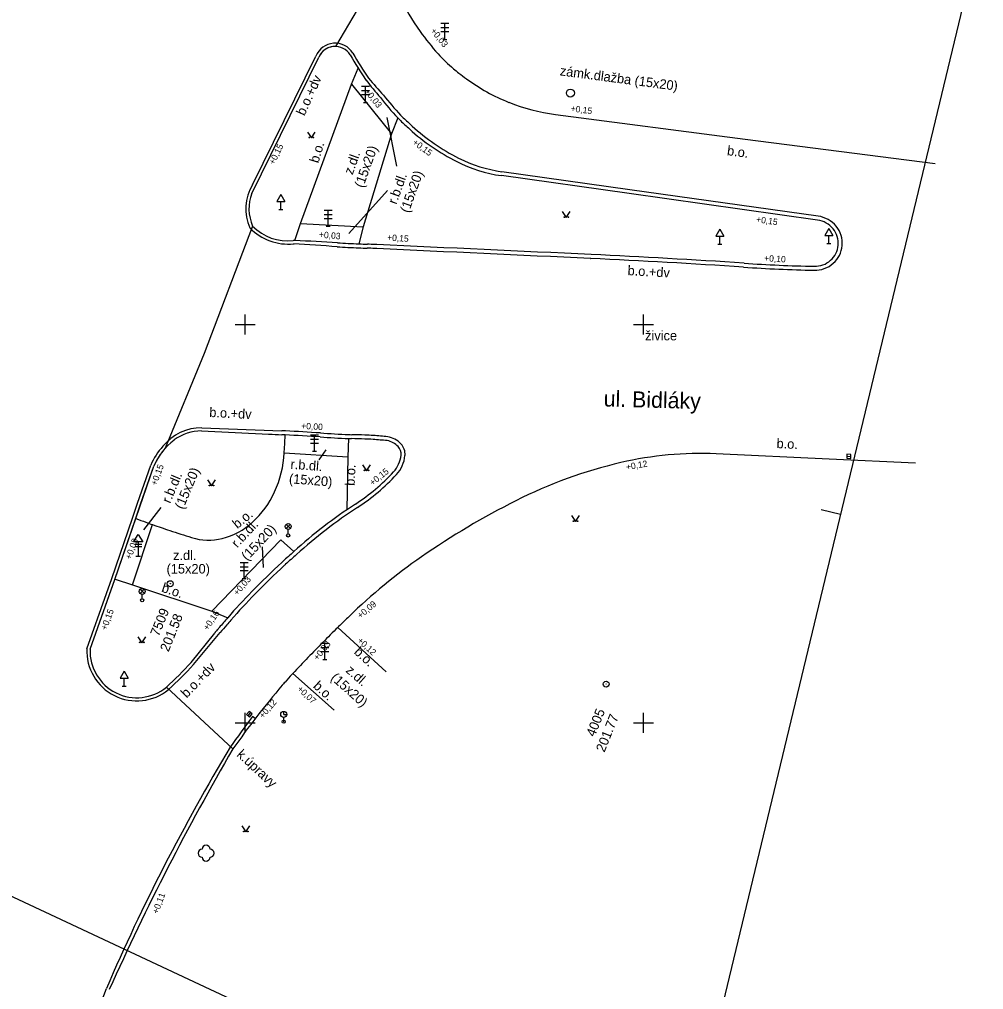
# Model space of a CAD drawing. Extents: x -599151 to -598424, y -1163476 to -1161924.
# Drawn here: x -598689.2 to -598628.7, y -1162691.7 to -1162630.9 of the extents above; entities that cross this region are included whole.
import ezdxf

# ---------------------------------------------------------------- set-up
doc = ezdxf.new("R2010")
doc.units = 0
for name, color, linetype in [('Vrstva 1', 7, 'Continuous'), ('Vrstva 14', 7, 'Continuous'), ('Vrstva 19', 7, 'Continuous'), ('Vrstva 2', 7, 'Continuous'), ('Vrstva 25', 7, 'Continuous'), ('Vrstva 29', 7, 'Continuous'), ('Vrstva 34', 7, 'Continuous'), ('Vrstva 42', 7, 'Continuous'), ('Vrstva 44', 7, 'Continuous'), ('Vrstva 49', 7, 'Continuous'), ('Vrstva 50', 7, 'Continuous'), ('Vrstva 62', 7, 'Continuous'), ('Vrstva 63', 7, 'Continuous'), ('Vrstva 7', 7, 'Continuous')]:
    doc.layers.add(name, color=color, linetype=linetype)

msp = doc.modelspace()

# ---------------------------------------------------------------- linework, layer by layer
at = {"layer": 'Vrstva 1'}
for p, q in [((-598563.987, -1162355.651), (-598649.916, -1162712.964)), ((-598637.64, -1162661.919), (-598638.855, -1162661.627)), ((-598640.084, -1162709.057), (-598707.36, -1162677.641))]:
    msp.add_line(p, q, dxfattribs=at)
at = {"layer": 'Vrstva 14'}
for points in [[(-598671.097, -1162637.921), (-598670.847, -1162638.296), (-598670.597, -1162637.921)], [(-598655.099, -1162642.92), (-598654.849, -1162643.295), (-598654.599, -1162642.92)], [(-598667.638, -1162658.805), (-598667.388, -1162659.18), (-598667.138, -1162658.805)], [(-598677.364, -1162659.751), (-598677.114, -1162660.126), (-598676.864, -1162659.751)], [(-598654.519, -1162661.988), (-598654.269, -1162662.363), (-598654.019, -1162661.988)], [(-598681.734, -1162669.597), (-598681.484, -1162669.972), (-598681.234, -1162669.597)], [(-598675.206, -1162681.467), (-598674.956, -1162681.842), (-598674.706, -1162681.467)]]:
    msp.add_lwpolyline(points, dxfattribs=at)
for centre, radius in [((-598670.972, -1162638.271), 0.025), ((-598670.722, -1162638.271), 0.025), ((-598654.974, -1162643.27), 0.025), ((-598654.724, -1162643.27), 0.025), ((-598667.513, -1162659.155), 0.025), ((-598667.263, -1162659.155), 0.025), ((-598677.239, -1162660.101), 0.025), ((-598676.989, -1162660.101), 0.025), ((-598654.394, -1162662.338), 0.025), ((-598654.144, -1162662.338), 0.025), ((-598681.609, -1162669.947), 0.025), ((-598681.359, -1162669.947), 0.025), ((-598675.081, -1162681.817), 0.025), ((-598674.831, -1162681.817), 0.025), ((-598677.45, -1162683.181), 0.00025)]:
    msp.add_circle(centre, radius, dxfattribs=at)
for centre, start, end in [((-598677.45, -1162682.931), 0, 179.99999), ((-598677.7, -1162683.181), 89.99999, 269.99999), ((-598677.2, -1162683.181), 270, 89.99999), ((-598677.45, -1162683.431), 179.99999, 359.99999)]:
    msp.add_arc(centre, 0.25, start, end, dxfattribs=at)
at = {"layer": 'Vrstva 19'}
for p, q in [((-598662.22, -1162631.121), (-598662.72, -1162631.121)), ((-598662.72, -1162631.371), (-598662.22, -1162631.371)), ((-598662.47, -1162632.121), (-598662.47, -1162631.121)), ((-598662.72, -1162631.621), (-598662.22, -1162631.621)), ((-598662.595, -1162632.121), (-598662.345, -1162632.121)), ((-598667.19, -1162635.07), (-598667.69, -1162635.07)), ((-598667.44, -1162636.07), (-598667.44, -1162635.07)), ((-598667.69, -1162635.32), (-598667.19, -1162635.32)), ((-598667.69, -1162635.57), (-598667.19, -1162635.57)), ((-598667.565, -1162636.07), (-598667.315, -1162636.07)), ((-598672.76, -1162641.847), (-598673.01, -1162642.28)), ((-598672.76, -1162641.847), (-598672.51, -1162642.28)), ((-598673.01, -1162642.28), (-598672.51, -1162642.28)), ((-598672.76, -1162642.78), (-598672.76, -1162642.28)), ((-598672.885, -1162642.78), (-598672.635, -1162642.78)), ((-598669.54, -1162642.84), (-598670.04, -1162642.84)), ((-598670.04, -1162643.09), (-598669.54, -1162643.09)), ((-598669.79, -1162643.84), (-598669.79, -1162642.84)), ((-598670.04, -1162643.34), (-598669.54, -1162643.34)), ((-598669.915, -1162643.84), (-598669.665, -1162643.84)), ((-598645.22, -1162644.017), (-598645.47, -1162644.45)), ((-598645.22, -1162644.017), (-598644.97, -1162644.45)), ((-598638.38, -1162643.978), (-598638.63, -1162644.411)), ((-598638.38, -1162643.978), (-598638.13, -1162644.411)), ((-598645.47, -1162644.45), (-598644.97, -1162644.45)), ((-598645.345, -1162644.95), (-598645.095, -1162644.95)), ((-598645.22, -1162644.95), (-598645.22, -1162644.45)), ((-598638.63, -1162644.411), (-598638.13, -1162644.411)), ((-598638.505, -1162644.911), (-598638.255, -1162644.911)), ((-598638.38, -1162644.911), (-598638.38, -1162644.411)), ((-598670.39, -1162656.95), (-598670.89, -1162656.95)), ((-598670.64, -1162657.95), (-598670.64, -1162656.95)), ((-598670.89, -1162657.2), (-598670.39, -1162657.2)), ((-598670.89, -1162657.45), (-598670.39, -1162657.45)), ((-598670.765, -1162657.95), (-598670.515, -1162657.95)), ((-598674.81, -1162664.95), (-598675.31, -1162664.95)), ((-598675.06, -1162665.95), (-598675.06, -1162664.95)), ((-598675.31, -1162665.2), (-598674.81, -1162665.2)), ((-598675.31, -1162665.45), (-598674.81, -1162665.45)), ((-598675.185, -1162665.95), (-598674.935, -1162665.95)), ((-598669.75, -1162670.02), (-598670.25, -1162670.02)), ((-598670.25, -1162670.27), (-598669.75, -1162670.27)), ((-598670.25, -1162670.52), (-598669.75, -1162670.52)), ((-598670, -1162671.02), (-598670, -1162670.02)), ((-598670.125, -1162671.02), (-598669.875, -1162671.02)), ((-598682.6, -1162671.757), (-598682.85, -1162672.19)), ((-598682.6, -1162671.757), (-598682.35, -1162672.19)), ((-598682.85, -1162672.19), (-598682.35, -1162672.19)), ((-598682.6, -1162672.69), (-598682.6, -1162672.19)), ((-598682.725, -1162672.69), (-598682.475, -1162672.69))]:
    msp.add_line(p, q, dxfattribs=at)
at = {"layer": 'Vrstva 2'}
for centre, radius in [((-598679.7, -1162666.27), 0.187), ((-598679.7, -1162666.27), 0.00896), ((-598652.35, -1162672.57), 0.187), ((-598652.35, -1162672.57), 0.00896)]:
    msp.add_circle(centre, radius, dxfattribs=at)
at = {"layer": 'Vrstva 25'}
for p, q in [((-598637.245, -1162658.264), (-598636.995, -1162658.276)), ((-598674.821, -1162674.555), (-598674.659, -1162674.365))]:
    msp.add_line(p, q, dxfattribs=at)
for points in [[(-598637.251, -1162658.389), (-598637.001, -1162658.401), (-598636.989, -1162658.151), (-598637.239, -1162658.139)], [(-598674.726, -1162674.636), (-598674.564, -1162674.446), (-598674.754, -1162674.284), (-598674.916, -1162674.474)]]:
    msp.add_lwpolyline(points, close=True, dxfattribs=at)
msp.add_circle((-598654.59, -1162635.48), 0.25, dxfattribs=at)
at = {"layer": 'Vrstva 29'}
for p, q in [((-598672.432, -1162662.809), (-598672.168, -1162662.545)), ((-598672.164, -1162662.808), (-598672.428, -1162662.543)), ((-598672.3, -1162663.14), (-598672.3, -1162662.865)), ((-598681.592, -1162666.879), (-598681.328, -1162666.615)), ((-598681.324, -1162666.878), (-598681.588, -1162666.613)), ((-598681.46, -1162667.21), (-598681.46, -1162666.935))]:
    msp.add_line(p, q, dxfattribs=at)
for centre, radius in [((-598672.3, -1162662.677), 0.188), ((-598672.3, -1162663.24), 0.1), ((-598681.46, -1162666.748), 0.188), ((-598681.46, -1162667.31), 0.1)]:
    msp.add_circle(centre, radius, dxfattribs=at)
at = {"layer": 'Vrstva 34'}
for p, q in [((-598672.58, -1162674.468), (-598672.58, -1162674.282)), ((-598672.58, -1162674.468), (-598672.393, -1162674.468)), ((-598672.58, -1162674.93), (-598672.58, -1162674.655))]:
    msp.add_line(p, q, dxfattribs=at)
for centre, radius in [((-598672.58, -1162674.468), 0.188), ((-598672.58, -1162674.93), 0.1), ((-598672.58, -1162674.468), 0.00025), ((-598672.58, -1162674.968), 0.00025)]:
    msp.add_circle(centre, radius, dxfattribs=at)
at = {"layer": 'Vrstva 44'}
for p, q in [((-598681.93, -1162663.79), (-598681.482, -1162663.79)), ((-598681.71, -1162663.64), (-598681.71, -1162664.54)), ((-598681.93, -1162663.94), (-598681.487, -1162663.94)), ((-598681.86, -1162664.54), (-598681.56, -1162664.54))]:
    msp.add_line(p, q, dxfattribs=at)
msp.add_lwpolyline([(-598682.01, -1162663.645), (-598681.71, -1162663.19), (-598681.41, -1162663.645)], close=True, dxfattribs=at)
at = {"layer": 'Vrstva 49'}
for p, q in [((-598666.102, -1162637.021), (-598665.504, -1162640.06)), ((-598668.495, -1162644.283), (-598666.077, -1162641.596)), ((-598681.348, -1162662.894), (-598680.268, -1162661.494))]:
    msp.add_line(p, q, dxfattribs=at)
for points in [[(-598669.93, -1162657.865), (-598670.383, -1162658.498)], [(-598673.851, -1162665.245), (-598673.911, -1162663.95)]]:
    msp.add_lwpolyline(points, dxfattribs=at)
at = {"layer": 'Vrstva 62'}
for p, q in [((-598675, -1162650.625), (-598675, -1162649.375)), ((-598650, -1162650.625), (-598650, -1162649.375)), ((-598675.625, -1162650), (-598674.375, -1162650)), ((-598650.625, -1162650), (-598649.375, -1162650)), ((-598675, -1162675.625), (-598675, -1162674.375)), ((-598650, -1162675.625), (-598650, -1162674.375)), ((-598675.625, -1162675), (-598674.375, -1162675)), ((-598650.625, -1162675), (-598649.375, -1162675))]:
    msp.add_line(p, q, dxfattribs=at)
at = {"layer": 'Vrstva 63'}
for points in [[(-598669.32, -1162632.55), (-598667.68, -1162629.8), (-598666.16, -1162626.73)], [(-598674.58, -1162641.77), (-598670.38, -1162633.23)], [(-598674.53, -1162643.83), (-598677.58, -1162651.82), (-598680.01, -1162657.77)], [(-598684.732, -1162670.383), (-598683.18, -1162666.01), (-598680.74, -1162658.9)], [(-598679.94, -1162672.76), (-598675.77, -1162676.64)]]:
    msp.add_lwpolyline(points, dxfattribs=at)
for centre, radius, start, end in [((-598669.357, -1162633.659), 1.11, 88.10906, 157.25205), ((-598672.059, -1162642.739), 2.701, 158.96263, 203.81817), ((-598676.727, -1162660.692), 4.395, 138.33361, 155.94004), ((-598681.8, -1162670.49), 2.934, 177.91559, 309.32495), ((-598538.305, -1162756.745), 159.102, 149.76932, 155.88541)]:
    msp.add_arc(centre, radius, start, end, dxfattribs=at)
at = {"layer": 'Vrstva 7'}
for p, q in [((-598668.33, -1162634.921), (-598665.81, -1162638.041)), ((-598650.902, -1162641.788), (-598658.92, -1162640.66)), ((-598650.867, -1162641.54), (-598658.885, -1162640.413)), ((-598639.08, -1162643.45), (-598650.902, -1162641.788)), ((-598639.045, -1162643.203), (-598650.867, -1162641.54)), ((-598671.52, -1162643.671), (-598667.59, -1162643.871)), ((-598653.292, -1162645.61), (-598653.29, -1162645.61)), ((-598653.322, -1162645.86), (-598653.32, -1162645.86)), ((-598672.55, -1162658.061), (-598668.55, -1162658.301)), ((-598682.07, -1162666.341), (-598680.81, -1162662.561)), ((-598677.1, -1162668.001), (-598672.76, -1162663.521)), ((-598672.76, -1162663.521), (-598671.95, -1162664.251))]:
    msp.add_line(p, q, dxfattribs=at)
for points in [[(-598674.58, -1162641.77), (-598670.38, -1162633.23)], [(-598674.539, -1162641.234), (-598670.566, -1162633.155)], [(-598671.88, -1162644.731), (-598671.52, -1162643.671), (-598668.33, -1162634.921), (-598667.918, -1162633.907)], [(-598665.43, -1162637.031), (-598665.81, -1162638.041), (-598667.59, -1162643.871), (-598667.86, -1162644.941)], [(-598655.53, -1162636.82), (-598643.62, -1162638.361), (-598631.71, -1162639.901)], [(-598677.717, -1162656.48), (-598672.696, -1162656.67)], [(-598677.73, -1162656.68), (-598673.51, -1162656.88)], [(-598672.55, -1162658.061), (-598672.519, -1162657.475), (-598672.49, -1162656.931)], [(-598668.51, -1162657.161), (-598668.55, -1162658.301), (-598668.617, -1162661.627)], [(-598632.94, -1162658.701), (-598638.354, -1162658.449), (-598645.44, -1162658.121)], [(-598684.931, -1162670.346), (-598683.699, -1162666.883), (-598683.369, -1162665.944), (-598682.06, -1162662.156), (-598681.75, -1162661.206), (-598680.926, -1162658.825)], [(-598684.732, -1162670.383), (-598683.51, -1162666.95), (-598683.18, -1162666.01), (-598681.87, -1162662.22), (-598681.56, -1162661.27), (-598680.74, -1162658.9)], [(-598683.16, -1162665.991), (-598682.07, -1162666.341), (-598677.1, -1162668.001), (-598676.09, -1162668.401)], [(-598678.239, -1162671.341), (-598676.559, -1162669.332)], [(-598666.16, -1162671.801), (-598669.19, -1162669.011)], [(-598678.39, -1162671.21), (-598676.911, -1162669.369)], [(-598672.01, -1162671.901), (-598669.41, -1162674.211)], [(-598674.381, -1162674.734), (-598674.54, -1162674.613)], [(-598690.36, -1162709.11), (-598686.141, -1162698.089), (-598683.709, -1162691.671)]]:
    msp.add_lwpolyline(points, dxfattribs=at)
for centre, radius, start, end in [((-598653.561, -1162624.029), 12.924, 204.3767, 215.93542), ((-598650.115, -1162621.542), 17.173, 215.90637, 221.892), ((-598669.357, -1162633.659), 1.31, 31.29055, 157.37934), ((-598669.357, -1162633.659), 1.11, 31.45639, 157.25205), ((-598650.812, -1162623.174), 20.195, 209.37584, 214.65452), ((-598650.812, -1162623.174), 19.995, 209.36589, 214.65452), ((-598655.572, -1162626.437), 9.842, 221.89197, 229.76297), ((-598655.159, -1162625.949), 10.481, 229.76297, 232.12501), ((-598638.785, -1162612.041), 36.492, 218.29802, 220.54935), ((-598639.324, -1162610.833), 36.641, 220.32382, 222.55147), ((-598649.422, -1162618.572), 19.827, 232.12502, 233.84233), ((-598653.9, -1162624.701), 12.236, 233.84233, 248.16326), ((-598652.247, -1162624.648), 18.086, 217.925, 223.20578), ((-598652.247, -1162624.648), 17.836, 217.925, 223.20578), ((-598653.992, -1162624.931), 11.988, 248.16326, 262.63236), ((-598662.323, -1162634.112), 4.263, 223.20578, 226.59114), ((-598662.323, -1162634.112), 4.013, 223.20578, 226.59114), ((-598638.084, -1162608.488), 39.285, 226.59114, 227.70264), ((-598638.084, -1162608.488), 39.535, 226.59114, 227.70264), ((-598655.617, -1162627.758), 13.232, 227.70264, 243.07859), ((-598655.617, -1162627.758), 13.482, 227.70264, 243.07859), ((-598657.676, -1162631.813), 8.935, 243.07859, 261.99527), ((-598657.676, -1162631.813), 8.685, 243.07859, 261.99527), ((-598672.059, -1162642.739), 2.901, 148.72714, 204.54925), ((-598672.059, -1162642.739), 2.701, 158.96263, 203.81817), ((-598639.292, -1162644.957), 1.521, 39.23012, 81.99527), ((-598639.292, -1162644.957), 1.771, 39.23012, 81.99527), ((-598672.305, -1162641.624), 3.333, 224.12604, 275.96159), ((-598672.305, -1162641.624), 3.133, 224.75924, 275.96159), ((-598639.24, -1162644.915), 1.455, 355.45238, 39.23012), ((-598639.24, -1162644.915), 1.705, 355.45238, 39.23012), ((-598667.761, -1162645.143), 4.203, 177.21575, 177.73531), ((-598672.265, -1162652.54), 7.819, 87.17692, 87.76628), ((-598691.841, -1162960.202), 315.889, 85.8952, 86.39136), ((-598687.056, -1162952.499), 308.142, 86.68076, 87.17692), ((-598664.601, -1162565.304), 79.703, 266.68076, 267.65635), ((-598648.577, -1162173.792), 471.543, 267.65635, 267.72093), ((-598681.327, -1162996.696), 352.013, 87.64617, 87.72093), ((-598667.933, -1162670.835), 25.877, 87.34362, 87.64617), ((-610317.485, -1413783.4), 251408.518, 87.34078611, 87.34385278), ((-598664.601, -1162565.304), 79.953, 266.68076, 267.65635), ((-598648.577, -1162173.792), 471.793, 267.65635, 267.72093), ((-598681.327, -1162996.696), 351.763, 87.64617, 87.72093), ((-598667.933, -1162670.835), 25.627, 87.34872, 87.64617), ((-600268.871, -1197242.563), 34634.402, 87.3264222, 87.3486556), ((-598675.066, -1163114.47), 469.365, 86.16827, 87.34079), ((-598639.187, -1162644.919), 1.402, 311.15905, 355.45238), ((-598639.187, -1162644.919), 1.652, 311.15905, 355.45238), ((-598674.423, -1163104.068), 458.693, 86.16279, 87.36306), ((-598637.104, -1162547.667), 98.708, 266.16827, 268.72524), ((-598639.266, -1162644.829), 1.771, 268.72524, 311.15905), ((-598639.266, -1162644.829), 1.521, 268.72524, 311.15905), ((-598637.104, -1162547.667), 98.958, 266.16279, 268.72524), ((-598677.71, -1162659.652), 3.172, 90.13717, 140.63379), ((-598677.71, -1162659.652), 2.972, 90.39308, 126.07893), ((-598659.357, -1162368.283), 288.944, 267.18726, 267.19244), ((-598268.328, -1154394.694), 8272.116, 267.1924389, 267.1979944), ((-598702.893, -1163273.632), 617.451, 87.177659, 87.197993), ((-598702.893, -1163273.632), 617.701, 87.177659, 87.197951), ((-598678.226, -1162773.276), 116.487, 86.09638, 87.17766), ((-598678.226, -1162773.276), 116.737, 86.09638, 87.17766), ((-598665.047, -1162580.147), 77.091, 266.09638, 267.42554), ((-598665.047, -1162580.147), 76.841, 266.09638, 267.42554), ((-598668.057, -1162647.085), 10.085, 267.42554, 268.4996), ((-598668.057, -1162647.085), 9.835, 267.42554, 268.4996), ((-598673.306, -1162847.483), 190.382, 88.2524, 88.4996), ((-598673.306, -1162847.483), 190.632, 88.2524, 88.4996), ((-598667.899, -1162670.269), 13.335, 85.94326, 88.2524), ((-598669.589, -1162694.101), 37.226, 84.55296, 85.94326), ((-598666.324, -1162658.539), 1.52, 43.71267, 79.80846), ((-598676.727, -1162660.692), 4.595, 138.38505, 156.02932), ((-598676.727, -1162660.692), 4.395, 128.45438, 155.94004), ((-598667.899, -1162670.269), 13.085, 85.94326, 88.2524), ((-598669.589, -1162694.101), 36.976, 84.5697, 85.94326), ((-598666.324, -1162658.539), 1.27, 43.71267, 79.36149), ((-598665.9, -1162658.134), 0.684, 354.39697, 43.71267), ((-598665.9, -1162658.134), 0.934, 354.39697, 43.71267), ((-598679.292, -1162657.702), 6.752, 335.41727, 356.9606), ((-598667.029, -1162658.023), 1.818, 335.8858, 354.39697), ((-598667.029, -1162658.023), 2.068, 335.8858, 354.39697), ((-598646.452, -1162679.935), 21.838, 87.34338, 103.16428), ((-598667.007, -1162658.033), 1.794, 317.25097, 335.8858), ((-598667.007, -1162658.033), 2.044, 317.25097, 335.8858), ((-598644.672, -1162687.546), 29.655, 103.16428, 116.72939), ((-598675.008, -1162650.637), 12.689, 303.09701, 317.25097), ((-598675.008, -1162650.637), 12.939, 303.09701, 317.25097), ((-598678.485, -1162658.072), 5.864, 312.27978, 335.41727), ((-598651.151, -1162687.238), 31, 123.09701, 132.13876), ((-598635.803, -1162705.158), 49.373, 116.72939, 124.73782), ((-598651.151, -1162687.238), 30.75, 123.09701, 132.13876), ((-598656.869, -1162595.739), 70.982, 249.39494, 249.92847), ((-598670.124, -1162632.016), 32.36, 249.92848, 250.71868), ((-598658.939, -1162600.041), 66.234, 250.71868, 251.70548), ((-598677.515, -1162659.138), 4.423, 284.10681, 312.27978), ((-598646.61, -1162562.751), 105.51, 251.70548, 252.48733), ((-598677.298, -1162660.004), 3.53, 252.48733, 284.10681), ((-598070.97, -1163328.464), 895.743, 132.138761, 132.19755), ((-598070.97, -1163328.464), 895.493, 132.138759, 132.197547), ((-598637.454, -1162703.023), 51.897, 132.77678, 135.66814), ((-598666.433, -1162671.703), 9.227, 132.19755, 132.77678), ((-598666.433, -1162671.703), 8.977, 132.19741, 132.77678), ((-598643.466, -1162694.107), 35.925, 124.73782, 134.12911), ((-598637.615, -1162702.85), 51.411, 132.77678, 135.66814), ((-598647.553, -1162693.158), 37.78, 135.66814, 139.05707), ((-598647.13, -1162693.554), 38.108, 135.66814, 139.02374), ((-598572.434, -1162758.326), 137.227, 139.05707, 139.39871), ((-598632.371, -1162706.373), 57.658, 139.02374, 139.39871), ((-597966.756, -1163391.708), 1007.822, 134.129105, 134.181544), ((-598611.132, -1162722.639), 84.644, 140.82551, 140.99889), ((-598670.65, -1162674.141), 7.868, 139.39871, 140.82551), ((-598654.014, -1162688.448), 29.558, 139.70698, 139.74843), ((-598552.826, -1162774.554), 162.424, 139.3987, 139.62243), ((-598535.951, -1162802.732), 188.77, 134.89643, 135.70236), ((-598665.362, -1162672.852), 5.423, 134.18155, 134.89643), ((-598681.8, -1162670.49), 3.134, 177.36524, 309.41558), ((-598681.8, -1162670.49), 2.934, 177.91559, 309.32495), ((-598634.414, -1162706.653), 51.198, 135.70237, 137.24994), ((-598694.599, -1162656.551), 21.854, 312.12528, 317.87472), ((-598694.599, -1162656.551), 22.054, 312.11276, 317.88586), ((-598442.59, -1162876.396), 307.331, 138.30172, 138.42441), ((-598668.932, -1162674.745), 4.191, 137.24994, 138.30187), ((-598631.725, -1162707.606), 53.841, 139.51009, 144.89106), ((-598637.616, -1162703.395), 46.631, 138.42264, 138.74436), ((-598631.564, -1162707.406), 54.059, 142.65419, 145.17544), ((-598564.765, -1162743.156), 129.609, 149.06819, 156.59448), ((-598538.305, -1162756.745), 159.102, 149.76932, 155.88541)]:
    msp.add_arc(centre, radius, start, end, dxfattribs=at)

# ---------------------------------------------------------------- texts
at = {"layer": 'Vrstva 2'}
for s, rotation, p in [('7509', 68.04899, (-598680.422, -1162669.619)), ('201.58', 68.19463, (-598679.808, -1162670.585)), ('4005', 68.04899, (-598653.072, -1162675.919)), ('201.77', 68.19463, (-598652.458, -1162676.885))]:
    msp.add_text(s, height=0.6, rotation=rotation, dxfattribs=at).set_placement(p)
at = {"layer": 'Vrstva 42'}
msp.add_text('ul. Bidláky', height=1, rotation=358.46757, dxfattribs=at).set_placement((-598652.515, -1162655.143))
at = {"layer": 'Vrstva 49'}
for s, rotation, p in [('zámk.dlažba (15x20)', 352.51118, (-598655.279, -1162634.362)), ('b.o.+dv', 65.59626, (-598671.278, -1162636.945)), ('b.o.', 73.02166, (-598670.409, -1162639.913)), ('(15x20)', 70.22229, (-598667.601, -1162641.462)), ('b.o.', 352.62763, (-598644.789, -1162639.369)), ('z.dl.', 70.22229, (-598668.262, -1162640.643)), ('r.b.dl.', 70.22229, (-598665.511, -1162642.5)), ('(15x20)', 70.22229, (-598664.737, -1162643.034)), ('b.o.+dv', 356.67329, (-598651.018, -1162646.901)), ('b.o.+dv', 357.09286, (-598677.262, -1162655.801)), ('b.o.', 357.34338, (-598641.67, -1162657.757)), ('r.b.dl.', 355.63686, (-598672.172, -1162659.053)), ('b.o.', 86.90385, (-598668.138, -1162660.138)), ('r.b.dl.', 67.32534, (-598679.708, -1162661.264)), ('(15x20)', 67.32534, (-598678.89, -1162661.641)), ('(15x20)', 355.63686, (-598672.266, -1162659.965)), ('b.o.', 38.92754, (-598675.495, -1162662.848)), ('r.b.dl.', 46.81216, (-598675.5, -1162664.048)), ('(15x20)', 46.81216, (-598674.87, -1162664.866)), ('b.o.', 341.53047, (-598680.29, -1162666.764)), ('b.o.', 317.36138, (-598668.211, -1162670.61)), ('b.o.+dv', 45.84848, (-598678.672, -1162673.475)), ('z.dl.', 318.38014, (-598668.731, -1162671.773)), ('b.o.', 317.36138, (-598670.774, -1162672.748)), ('(15x20)', 318.38014, (-598669.676, -1162672.244)), ('k.úpravy', 317.06318, (-598675.569, -1162677.051))]:
    msp.add_text(s, height=0.6, rotation=rotation, dxfattribs=at).set_placement(p)
for s, p in [('živice', (-598649.907, -1162650.997)), ('z.dl.', (-598679.522, -1162664.783)), ('(15x20)', (-598679.932, -1162665.631))]:
    msp.add_text(s, height=0.6, dxfattribs=at).set_placement(p)
at = {"layer": 'Vrstva 50'}
for s, rotation, p in [('+0,03', 308.6323, (-598663.391, -1162631.589)), ('+0,03', 308.6323, (-598667.537, -1162635.393)), ('+0,15', 352.62763, (-598654.594, -1162636.63)), ('+0,15', 63.81189, (-598673.18, -1162640.006)), ('+0,15', 323.4829, (-598664.536, -1162638.65)), ('+0,15', 351.9975, (-598642.957, -1162643.587)), ('+0,03', 355.23661, (-598670.38, -1162644.547)), ('+0,15', 356.28362, (-598666.102, -1162644.732)), ('+0,10', 356.28362, (-598642.445, -1162646.026)), ('+0,00', 356.69262, (-598671.489, -1162656.556)), ('+0,15', 69.52772, (-598680.565, -1162660.138)), ('+0,15', 38.92754, (-598666.998, -1162660.141)), ('+0,12', 9.84141, (-598651.067, -1162659.148)), ('+0,03', 69.52772, (-598682.171, -1162664.783)), ('+0,03', 49.59718, (-598675.481, -1162667.043)), ('+0,09', 39.89925, (-598667.762, -1162668.48)), ('+0,15', 69.52772, (-598683.701, -1162669.22)), ('+0,16', 56.20418, (-598677.338, -1162669.236)), ('+0,03', 51.33596, (-598670.451, -1162671.115)), ('+0,12', 317.36138, (-598668, -1162669.887)), ('+0,07', 317.36138, (-598671.769, -1162672.929)), ('+0,12', 49.66719, (-598673.868, -1162674.758)), ('+0,11', 69.52772, (-598680.471, -1162687.025))]:
    msp.add_text(s, height=0.4, rotation=rotation, dxfattribs=at).set_placement(p)

doc.saveas('drawing.dxf')
